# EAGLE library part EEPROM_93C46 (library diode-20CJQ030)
IC SERIAL EEPROM 1K 64X16 8SOIC 1K (64 x 16) 2MHz Microwire 3-Wire Serial 8SOIC package digikey part#: 93C46B/SN-ND microchip part#: 93C46B/SN
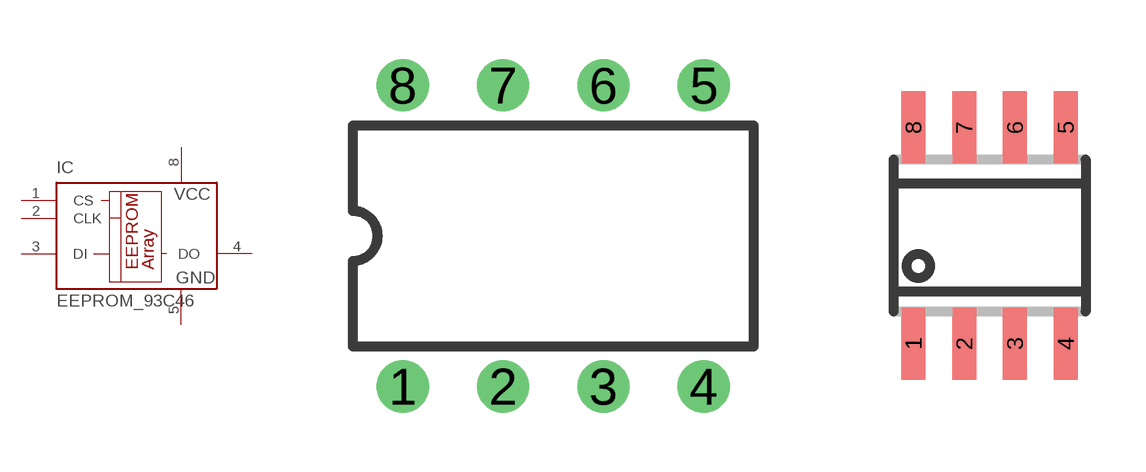
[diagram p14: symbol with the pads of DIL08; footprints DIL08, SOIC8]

Designator prefix IC

## EEPROM_93C46D  [DIL08]
1  CS  in
2  CLK  in
3  DI  in
4  DO  hiz
5  GND  pwr
8  VCC  pwr

## EEPROM_93C46S  [SOIC8]
Pads as for DIL08

## Footprint DIL08 (pad centres in mm)
Dual In Line
drill 0.813 round: 1 -3.81,-3.81; 2 -1.27,-3.81; 3 1.27,-3.81; 4 3.81,-3.81; 5 3.81,3.81; 6 1.27,3.81; 7 -1.27,3.81; 8 -3.81,3.81

## Footprint SOIC8 (pad centres in mm)
Small Outline IC
smd 0.6 x 1.8: 1 -1.905,-2.7; 2 -0.635,-2.7; 3 0.635,-2.7; 4 1.905,-2.7; 5 1.905,2.7; 6 0.635,2.7; 7 -0.635,2.7; 8 -1.905,2.7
